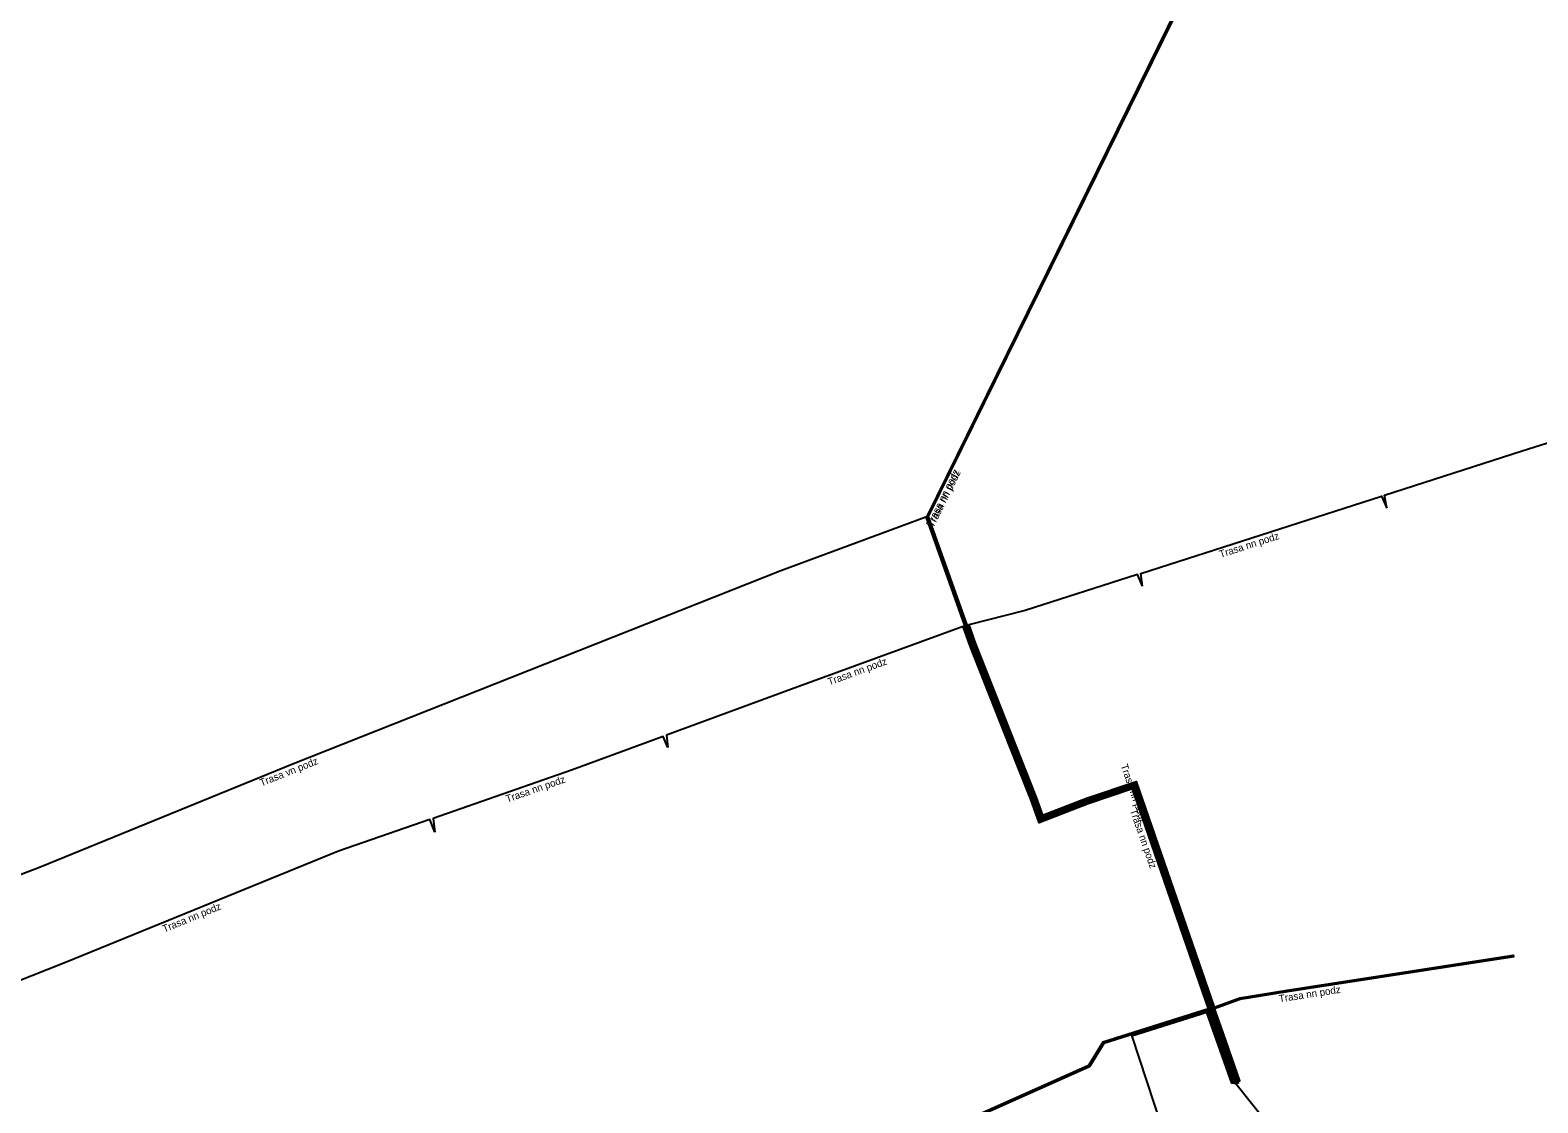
# Model space of a CAD drawing. Extents: x -873583 to -872966, y -1012951 to -1012536.
# Drawn here: x -873381.3 to -873277.8, y -1012796.7 to -1012723 of the extents above; entities that cross this region are included whole.
import ezdxf

# ---------------------------------------------------------------- set-up
doc = ezdxf.new("R2010")
doc.units = 0
for name, color, linetype in [('Popiskový text - Ostatní atributy Trasy', 7, 'Continuous'), ('Spojnice NN', 7, 'Continuous'), ('Spojnice VN', 7, 'Continuous')]:
    doc.layers.add(name, color=color, linetype=linetype)

msp = doc.modelspace()

# ---------------------------------------------------------------- linework, layer by layer
at = {"layer": 'Spojnice NN'}
for points in [[(-873298.55, -1012795.35), (-873298.45, -1012795.21), (-873299.78, -1012791.45), (-873305.53, -1012774.85), (-873308.74, -1012775.94), (-873311.94, -1012777.18), (-873312.45, -1012775.77), (-873316.6, -1012765.23), (-873319.74, -1012756.4), (-873299.78, -1012715.82), (-873300.34, -1012705.54), (-873299.89, -1012705.3)], [(-873298.55, -1012795.35), (-873298.36, -1012795.17), (-873299.69, -1012791.42), (-873305.47, -1012774.73), (-873308.78, -1012775.84), (-873311.88, -1012777.05), (-873312.35, -1012775.74), (-873316.51, -1012765.19), (-873319.64, -1012756.41), (-873299.68, -1012715.84), (-873300.24, -1012705.62), (-873299.89, -1012705.3)], [(-873288.19, -1012755.84), (-873288.36, -1012754.95), (-873278.91, -1012751.91), (-873264.77, -1012747.45), (-873257.51, -1012745.8), (-873257.15, -1012746.87)], [(-873304.96, -1012761.2), (-873305.08, -1012760.33), (-873288.56, -1012755.01), (-873288.19, -1012755.84)], [(-873304.96, -1012761.2), (-873305.31, -1012760.38), (-873313.01, -1012762.86), (-873316.89, -1012763.84), (-873316.42, -1012765.16), (-873312.26, -1012775.7), (-873311.82, -1012776.92), (-873308.81, -1012775.75), (-873305.4, -1012774.6), (-873300.04, -1012790.09), (-873298.27, -1012789.44), (-873295.03, -1012788.92), (-873279.53, -1012786.53), (-873279.46, -1012786.61)], [(-873314.09, -1012772.15), (-873316.79, -1012765.3), (-873317.27, -1012763.97), (-873329.06, -1012768.27), (-873337.63, -1012771.43), (-873337.53, -1012772.27)], [(-873337.53, -1012772.27), (-873337.86, -1012771.52), (-873344.14, -1012773.83), (-873353.65, -1012777.13), (-873353.52, -1012778.08)], [(-873298.55, -1012795.35), (-873298.55, -1012795.24), (-873299.97, -1012791.52), (-873305.65, -1012775.1), (-873308.68, -1012776.13), (-873312.06, -1012777.44), (-873312.63, -1012775.84), (-873314.09, -1012772.15)], [(-873353.52, -1012778.08), (-873353.86, -1012777.21), (-873360.14, -1012779.39), (-873378.87, -1012787.03), (-873384.74, -1012789.34), (-873384.56, -1012790.44)], [(-873298.55, -1012795.35), (-873298.27, -1012795.14), (-873299.59, -1012791.39), (-873300.01, -1012790.19), (-873298.25, -1012789.54), (-873295.01, -1012789.02), (-873279.46, -1012786.61)], [(-873298.55, -1012795.35), (-873298.64, -1012795.28), (-873300.42, -1012790.21), (-873304.64, -1012791.54), (-873307.69, -1012792.49), (-873308.66, -1012794.1), (-873337.9, -1012807.16), (-873363.37, -1012817.16), (-873365.27, -1012816.84)], [(-873298.55, -1012795.35), (-873298.73, -1012795.31), (-873300.49, -1012790.34), (-873307.62, -1012792.58), (-873308.59, -1012794.18), (-873337.86, -1012807.25), (-873363.24, -1012817.22), (-873364.94, -1012817.43)], [(-873298.55, -1012795.35), (-873298.84, -1012795.31), (-873300.55, -1012790.46), (-873305.7, -1012792.08), (-873303.16, -1012799.82), (-873296.49, -1012810.21), (-873287.78, -1012831.11), (-873282.8, -1012842.92), (-873285.56, -1012844.42)]]:
    msp.add_lwpolyline(points, dxfattribs=at)
at = {"layer": 'Spojnice VN'}
for points in [[(-873437.43, -1012765.02), (-873434.85, -1012771.67), (-873429.23, -1012781.85), (-873420.43, -1012795.44), (-873413.32, -1012792.95), (-873380.66, -1012780.47), (-873363.22, -1012773.36), (-873329.78, -1012760.12), (-873319.84, -1012756.43), (-873316.7, -1012765.26), (-873312.54, -1012775.81), (-873312, -1012777.31), (-873308.71, -1012776.03), (-873305.59, -1012774.98), (-873299.88, -1012791.49), (-873298.4, -1012795.35)], [(-873272.1, -1012828.56), (-873298.55, -1012795.35)]]:
    msp.add_lwpolyline(points, dxfattribs=at)

# ---------------------------------------------------------------- texts
at = {"layer": 'Popiskový text - Ostatní atributy Trasy'}
for s, rotation, p in [('Trasa nn podz', 63.8011, (-873319.39, -1012757.14)), ('Trasa nn podz', 63.8007, (-873319.31, -1012757.22)), ('Trasa nn podz', 17.8289, (-873299.6, -1012759.25)), ('Trasa nn podz', 20.0231, (-873326.46, -1012768.01)), ('Trasa vn podz', 21.5992, (-873365.43, -1012774.94)), ('Trasa nn podz', 289.0924, (-873306.47, -1012773.5)), ('Trasa nn podz', 19.1465, (-873348.56, -1012776.05)), ('Trasa nn podz', 289.0887, (-873305.83, -1012776.58)), ('Trasa nn podz', 22.2081, (-873372.1, -1012784.97)), ('Trasa nn podz', 8.8053, (-873295.56, -1012789.76))]:
    msp.add_text(s, height=0.5, rotation=rotation, dxfattribs=at).set_placement(p)

doc.saveas('drawing.dxf')
